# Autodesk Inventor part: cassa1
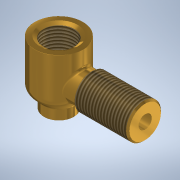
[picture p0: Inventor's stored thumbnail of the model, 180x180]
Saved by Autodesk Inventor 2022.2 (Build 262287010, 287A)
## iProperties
Created: 2014-01
Part Number: cassa1
Document SubType Name: Modeling
Designer: UTENTE
Density: 8.47 g/cm^3
Material: Ottone, Giallo chiaro
Appearance: Ottone - Satinato
Author: UTENTE
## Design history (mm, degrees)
sketch "Schizzo1"
  geometry: C1 r 9 at (0, 0); 1 further point
  constraints: 1 centre point, 1 coincident
extrude "Estrusione1" new body sketch "Schizzo1" distance "d1" = 6; taper "d2" = 0 deg
sketch "Schizzo2"
  geometry: C1 r 9 at (0, 0) reference; C2 r 14.5 at (0, 0)
  constraints: 1 centre point, 1 coincident
extrude "Estrusione2" join sketch "Schizzo2" distance "d4" = 32; taper "d5" = 0 deg
sketch "Schizzo3"
  geometry: C1 r 9 at (0, 0) reference; C2 r 6 at (0, 0)
  constraints: 1 centre point, 1 coincident
extrude "Estrusione3" cut sketch "Schizzo3" distance "d7" = 13; taper "d8" = 0 deg
sketch "Schizzo4"
  geometry: C1 r 6 at (0, 0) reference; C2 r 11 at (0, 0)
  constraints: 1 centre point, 1 coincident
extrude "Estrusione4" cut sketch "Schizzo4" distance "d10" = 11; taper "d11" = 0 deg
hole "Hole1" diameter "d14" = 18.631; stored, may be unused: countersink angle "d18" = 90 deg, drill point angle "d20" = 118 deg; dims "d12" = 10, "d13" = 10, "d15" = 6, "d16" = 4, "d17" = 2, "d19" = 23
chamfer "Smusso1" distance "d21" = 0.5; stored, may be unused: second distance "d22" = 2, angle "d23" = 45 deg
fillet "Raccordo1" dims "d24" = 2
chamfer "Smusso2" distance "d25" = 2; stored, may be unused: second distance "d26" = 2, angle "d27" = 30 deg
chamfer "Smusso3" distance "d28" = 5.5; stored, may be unused: second distance "d29" = 2, angle "d30" = 45 deg
fillet "Raccordo2" dims "d31" = 6
fillet "Raccordo3" dims "d32" = 1
sketch "Schizzo5"
  geometry: L1 (-11.316, 38)-(-9.316, 36.845) reference; L2 (-9.316, 36.845)-(-9.316, 24) reference; L3 (-11, 22.025)-(-11, 15) reference; L4 (-9, 13)-(-6.5, 13) reference; L5 (-6.5, 13)-(-6, 12.5) reference; L6 (-6, 12.5)-(-6, 0) reference; L7 (-6, 0)-(-9, 0) reference; L8 (-9, 0)-(-9, 5.586) reference; L9 (-9.293, 6.293)-(-12.743, 9.743) reference; L10 (-14.5, 13.985)-(-14.5, 38) reference; L11 (-14.5, 38)-(-11.316, 38) reference; L12 (9.316, 36.845)-(11.316, 38) reference; L13 (11.316, 38)-(14.5, 38) reference; L14 (14.5, 38)-(14.5, 13.985) reference; L15 (12.743, 9.743)-(9.293, 6.293) reference; L16 (9, 5.586)-(9, 0) reference; L17 (9, 0)-(6, 0) reference; L18 (6, 0)-(6, 12.5) reference; L19 (6, 12.5)-(6.5, 13) reference; L20 (6.5, 13)-(9, 13) reference; L21 (11, 15)-(11, 22.025) reference; L22 (9.316, 24)-(9.316, 36.845) reference; A1 r 2 centre (-9, 22.025) between (-9.316, 24) and (-11, 22.025) reference; A2 r 2 centre (-9, 15) between (-11, 15) and (-9, 13) reference; A3 r 1 centre (-10, 5.586) between (-9, 5.586) and (-9.293, 6.293) reference; A4 r 6 centre (-8.5, 13.985) between (-14.5, 13.985) and (-12.743, 9.743) reference; A5 r 6 centre (8.5, 13.985) between (12.743, 9.743) and (14.5, 13.985) reference; A6 r 1 centre (10, 5.586) between (9.293, 6.293) and (9, 5.586) reference; A7 r 2 centre (9, 15) between (9, 13) and (11, 15) reference; A8 r 2 centre (9, 22.025) between (11, 22.025) and (9.316, 24) reference; 1 further point
  node "Proietta spigoli di taglio1"
node "Piano di lavoro1"
sketch "Schizzo6"
  geometry: C1 r 9 at (0, 19); 1 further point
  constraints: 1 centre point
extrude "Estrusione5" join sketch "Schizzo6" stored distance "d37" = 0; taper "d38" = 0 deg
sketch "Schizzo7"
  geometry: C1 r 9 at (0, 19) reference; C2 r 10.498 at (0, 19); 1 further point
  constraints: 1 centre point, 1 coincident
extrude "Estrusione6" join sketch "Schizzo7" distance "d40" = 32; taper "d41" = 0 deg
hole "Hole2" diameter "d44" = 8; stored, may be unused: countersink angle "d48" = 90 deg, drill point angle "d50" = 118 deg; dims "d42" = 10, "d43" = 10, "d45" = 6, "d46" = 4, "d47" = 2, "d49" = 52
feature "Filettatura1" dims "d51" = 10, "d52" = 0
chamfer "Smusso4" distance "d53" = 1; stored, may be unused: second distance "d54" = 2, angle "d55" = 45 deg
fillet "Raccordo4" dims "d56" = 1.5
chamfer "Smusso5" distance "d57" = 1; stored, may be unused: second distance "d58" = 2, angle "d59" = 30 deg
fillet "Raccordo5" dims "d60" = 1.5
chamfer "Smusso6" distance "d61" = 0.1; stored, may be unused: second distance "d62" = 2, angle "d63" = 45 deg
node "Solido1"
node "Proietta spigoli di taglio2"
other parameters: "d34" = 52
